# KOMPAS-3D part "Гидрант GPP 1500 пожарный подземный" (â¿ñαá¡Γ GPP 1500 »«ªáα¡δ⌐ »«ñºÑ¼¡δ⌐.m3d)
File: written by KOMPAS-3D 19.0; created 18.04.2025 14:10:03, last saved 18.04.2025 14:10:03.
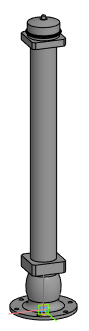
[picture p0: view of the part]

Document properties: Полное имя файла: E:\Dendor Работа Сачек\3D для проекитирвщиков\11.1 Тип GPP. Гидрант пожарный подземный\stp_Тип GPP. 750-6000 Гидрант пожарный подземный\Гидрант GPP 1500 пожарный подземный.m3d

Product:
- Part/product: Гидрант GPP 1500 пожарный подземный

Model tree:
1. Операция без истории:1  (labels: Гидрант GPP 1500 пожарный подземный)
